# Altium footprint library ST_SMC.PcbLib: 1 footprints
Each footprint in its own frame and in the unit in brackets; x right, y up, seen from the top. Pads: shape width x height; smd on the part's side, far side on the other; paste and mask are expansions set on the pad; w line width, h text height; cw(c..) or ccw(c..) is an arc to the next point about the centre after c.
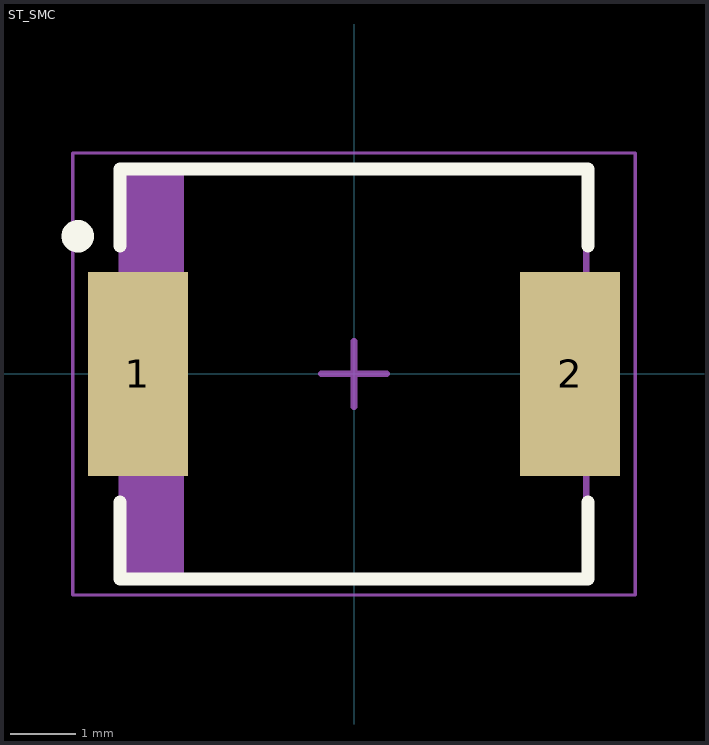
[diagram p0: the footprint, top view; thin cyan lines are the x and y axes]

## ST_SMC [mm] "ST_SMC"
height 2.65
pads (2):
  rect 1.54x3.14 smd: 1(-3.325,0) 2(3.325,0)
Top Overlay:
  circle w0.25: c-4.25,2.12 r0.125
  lines w0.2: -3.6,-1.97 -3.6,-3.15 3.6,-3.15 3.6,-1.97 ; -3.6,1.97 -3.6,3.15 3.6,3.15 3.6,1.97
Mechanical 13:
  rectangle: -3.575,-3.125 -2.613,3.125
  lines w0.1: -3.575,-3.125 3.575,-3.125 3.575,3.125 -3.575,3.125 -3.575,-3.125
Mechanical 15:
  lines w0.05: -4.325,-3.4 4.325,-3.4 4.325,3.4 -4.325,3.4 -4.325,-3.4
  lines w0.1: -0.5,0 0.5,0 ; 0,-0.5 0,0.5
3D body "ST_SMC.step": height 2.65, standoff 0, extent -3.795,-3.125 3.795,3.125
